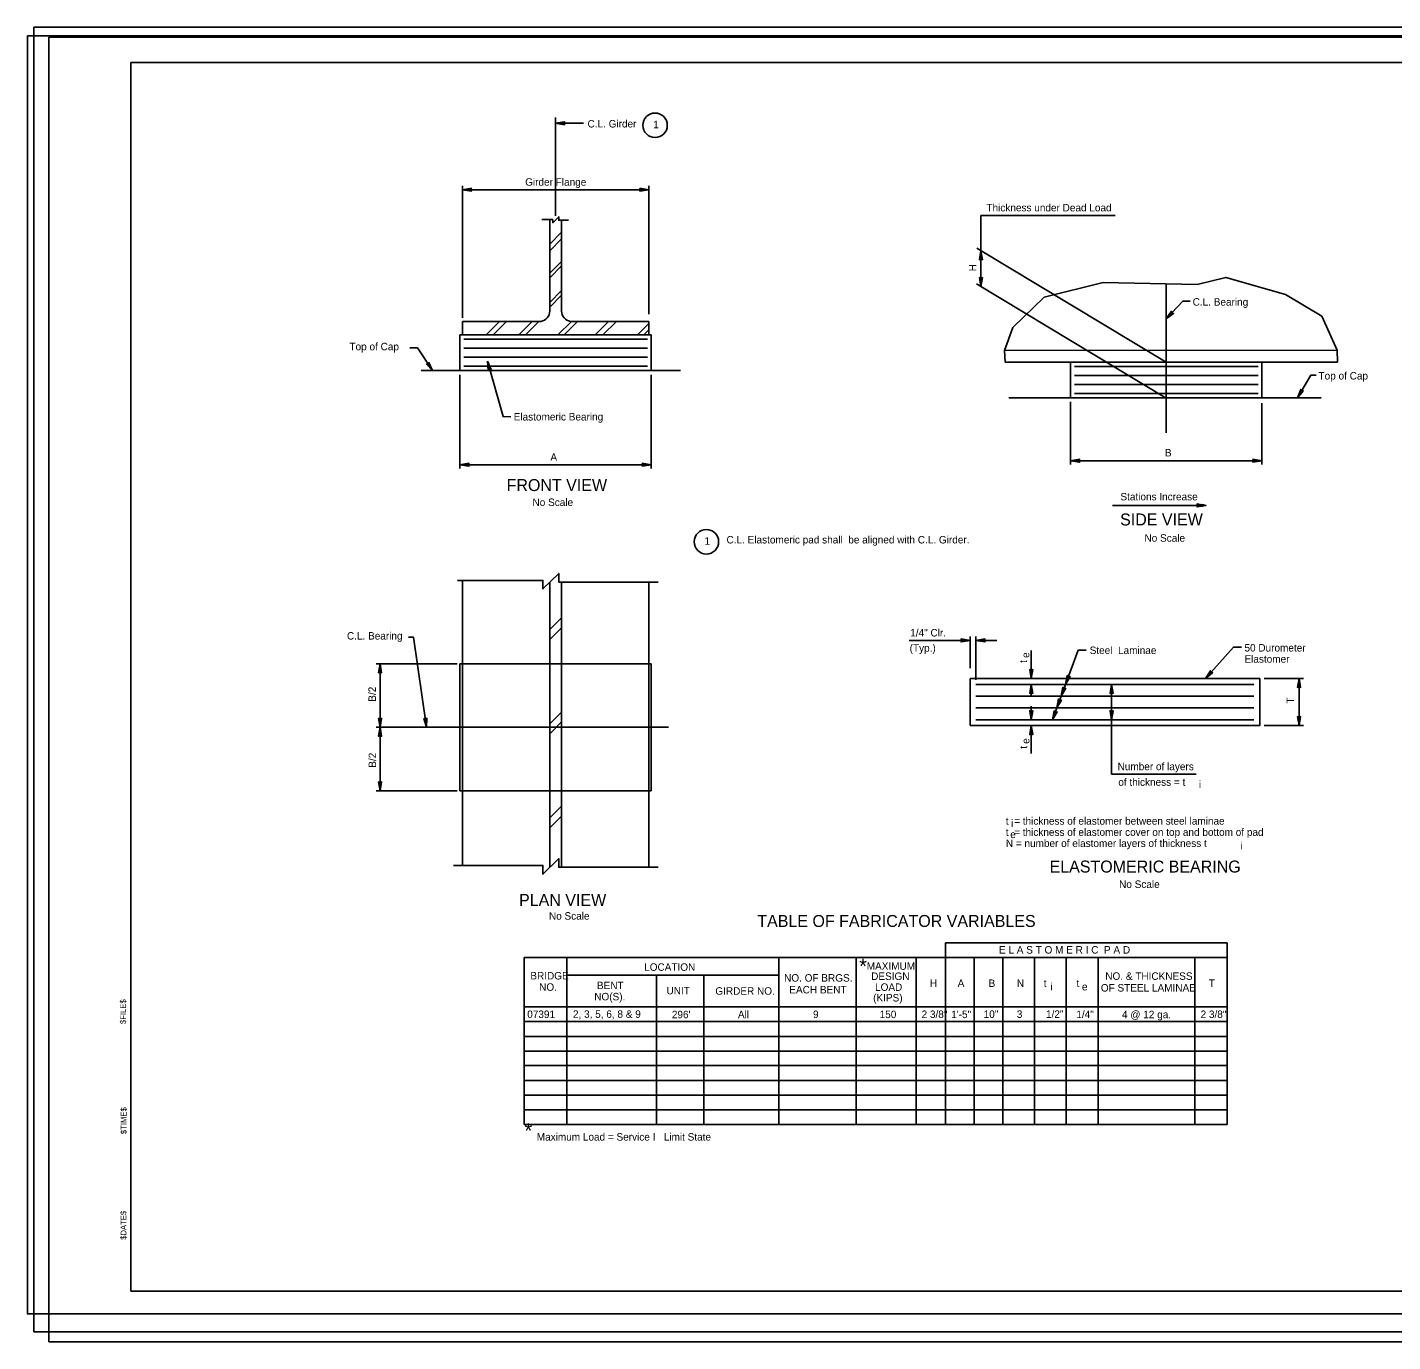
# Model space of a CAD drawing. Extents: x -194 to 226, y 505 to 725.
# Drawn here: x -193.6 to 34.6, y 505.4 to 725.2 of the extents above; entities that cross this region are included whole.
import ezdxf

# ---------------------------------------------------------------- set-up
doc = ezdxf.new("R2010")
doc.units = 0
for name, color, linetype in [('border', 7, 'Continuous'), ('Border 2660-Hwy18 - Level 62', 7, 'Continuous'), ('Border 2660-Hwy18 - Level 63', 7, 'Continuous'), ('Dimensions', 7, 'Continuous'), ('Level 20', 7, 'Continuous'), ('Level 21', 7, 'Continuous'), ('Level 31', 7, 'Continuous'), ('Level 40', 7, 'Continuous'), ('Level 41', 7, 'Continuous'), ('Level 42', 7, 'Continuous'), ('Level 43', 7, 'Continuous'), ('Level 58', 7, 'Continuous'), ('Level 62 PDF', 7, 'Continuous')]:
    doc.layers.add(name, color=color, linetype=linetype)

# ---------------------------------------------------------------- blocks, each defined once
blk = doc.blocks.new('ARROW')
at = {"layer": 'Level 58'}
blk.add_lwpolyline([(-1.2, 0.251), (0, 0), (-1.2, -0.251), (-1.004, 0)], close=True, dxfattribs=at)

msp = doc.modelspace()

# ---------------------------------------------------------------- linework, layer by layer
at = {"layer": 'border'}
for p, q in [((-176.33, 719.31), (143.78, 719.31)), ((-176.33, 513.86), (-176.33, 719.31)), ((143.78, 513.86), (-176.33, 513.86))]:
    msp.add_line(p, q, dxfattribs=at)
at = {"layer": 'Border 2660-Hwy18 - Level 62'}
msp.add_lwpolyline([(-192.53, 725.17), (148.65, 725.17), (148.65, 507.07), (-192.53, 507.07)], close=True, dxfattribs=at)
at = {"layer": 'Border 2660-Hwy18 - Level 63'}
msp.add_lwpolyline([(-193.64, 723.74), (146.35, 723.74), (146.35, 510.04), (-193.64, 510.04)], close=True, dxfattribs=at)
at = {"layer": 'Dimensions'}
for p, q in [((-129.69, 671.58), (-128.41, 671.58)), ((-128.41, 671.58), (-125.92, 667.79))]:
    msp.add_line(p, q, dxfattribs=at)
msp.add_lwpolyline([(-125.92, 667.79), (-126.51, 669.12), (-126.64, 668.89), (-126.91, 668.86)], close=True, dxfattribs=at)
at = {"layer": 'Level 20'}
for p, q in [((-105.35, 693.67), (-105.35, 710.08)), ((-3.29, 657.38), (-3.29, 682.35)), ((-135.32, 608.13), (-86.47, 608.13))]:
    msp.add_line(p, q, dxfattribs=at)
at = {"layer": 'Level 21'}
for p, q in [((-84.47, 667.79), (-127.81, 667.79)), ((22.62, 663.21), (-29.62, 663.21))]:
    msp.add_line(p, q, dxfattribs=at)
at = {"layer": 'Level 31'}
for p, q in [((-106.33, 693.03), (-106.33, 677.74)), ((-104.36, 692.92), (-104.36, 677.74)), ((-107.8, 675.98), (-120.93, 675.98)), ((-120.93, 673.75), (-120.93, 675.98)), ((-102.89, 675.98), (-89.76, 675.98)), ((-89.76, 673.75), (-89.76, 675.98)), ((-121.33, 673.75), (-104.36, 673.75)), ((-121.33, 667.79), (-121.33, 673.75)), ((-89.37, 673.75), (-106.33, 673.75)), ((-89.37, 667.79), (-89.37, 673.75)), ((-120.68, 673.01), (-90.01, 673.01)), ((-120.68, 671.52), (-90.01, 671.52)), ((-30.3, 671.15), (25.29, 671.16)), ((-120.68, 670.02), (-90.01, 670.02)), ((-30.24, 669.17), (25.35, 669.19)), ((-19.27, 663.21), (-19.27, 669.17)), ((12.69, 663.21), (12.69, 669.17)), ((-120.68, 668.53), (-90.01, 668.53)), ((-18.62, 668.43), (12.05, 668.43)), ((-18.62, 666.94), (12.05, 666.94)), ((-18.62, 665.45), (12.05, 665.45)), ((-18.62, 663.95), (12.05, 663.95)), ((-120.93, 585.03), (-120.93, 632.7)), ((-106.33, 632.38), (-106.33, 584.69)), ((-104.36, 632.42), (-104.36, 584.74)), ((-89.76, 584.74), (-89.76, 632.42)), ((-121.33, 618.76), (-121.33, 597.5)), ((-120.93, 618.76), (-121.33, 618.76)), ((-120.93, 618.76), (-89.76, 618.76)), ((-89.76, 618.76), (-89.37, 618.76)), ((-89.37, 618.76), (-89.37, 597.5)), ((-36.07, 616.29), (12.33, 616.29)), ((-36.07, 616.29), (-36.07, 608.42)), ((12.33, 616.29), (12.33, 608.42)), ((-35.09, 615.31), (11.33, 615.31)), ((-35.09, 613.34), (-20.87, 613.34)), ((-20.87, 613.34), (11.33, 613.34)), ((-35.09, 611.37), (11.33, 611.37)), ((-35.09, 609.4), (-22.31, 609.4)), ((-22.31, 609.4), (11.33, 609.4)), ((-36.07, 608.42), (12.33, 608.42)), ((-120.93, 597.5), (-121.33, 597.5)), ((-120.93, 597.5), (-89.76, 597.5)), ((-89.76, 597.5), (-89.37, 597.5))]:
    msp.add_line(p, q, dxfattribs=at)
for centre, start, end in [((-108.1, 677.73), 279.5, 0), ((-102.59, 677.73), 180, 260.5)]:
    msp.add_arc(centre, 1.76, start, end, dxfattribs=at)
at = {"layer": 'Level 40'}
for p, q in [((-103.46, 569.66), (-103.46, 541.74)), ((-68.06, 569.66), (-68.06, 541.74)), ((-55.1, 569.66), (-55.1, 541.74)), ((-45.11, 569.66), (-45.11, 541.74)), ((-35.38, 569.66), (-35.38, 541.74)), ((-30.59, 569.66), (-30.59, 541.74)), ((-25.3, 569.66), (-25.3, 541.74)), ((-20.03, 569.66), (-20.03, 541.74)), ((-14.65, 569.66), (-14.65, 541.74)), ((1.49, 569.66), (1.49, 541.74)), ((-103.46, 566.68), (-68.06, 566.68)), ((-88.46, 566.68), (-88.46, 541.74)), ((-80.56, 566.68), (-80.56, 541.74)), ((-110.62, 561.37), (6.87, 561.37)), ((6.87, 561.87), (6.87, 558.38)), ((-110.62, 558.92), (6.87, 558.92)), ((-110.62, 556.46), (6.87, 556.46)), ((-110.62, 554.01), (6.87, 554.01)), ((-110.62, 551.56), (6.87, 551.56)), ((-110.62, 549.1), (6.87, 549.1)), ((-110.62, 546.65), (6.87, 546.65)), ((-110.62, 544.2), (6.87, 544.2))]:
    msp.add_line(p, q, dxfattribs=at)
for centre in [(-88.73, 708.78), (-80.15, 639.15)]:
    msp.add_circle(centre, 2.05, dxfattribs=at)
at = {"layer": 'Level 41'}
for p, q in [((-40.17, 572.11), (-40.17, 541.74)), ((-40.17, 572.11), (6.87, 572.11)), ((6.87, 572.11), (6.87, 541.74)), ((-110.62, 569.66), (6.87, 569.66)), ((-110.62, 569.66), (-110.62, 541.74)), ((-110.62, 541.74), (6.87, 541.74))]:
    msp.add_line(p, q, dxfattribs=at)
at = {"layer": 'Level 42'}
for p, q in [((-106.33, 688.92), (-104.36, 690.89)), ((-106.33, 687.82), (-104.36, 689.81)), ((-106.33, 684.07), (-104.36, 686.03)), ((-106.33, 683.3), (-104.36, 685.27)), ((-106.33, 679.18), (-104.36, 681.15)), ((-106.33, 678.37), (-104.36, 680.37)), ((-116.93, 673.75), (-114.7, 675.98)), ((-115.8, 673.75), (-113.57, 675.98)), ((-111.5, 673.75), (-109.28, 675.98)), ((-110.4, 673.75), (-108.18, 675.98)), ((-104.95, 673.75), (-102.71, 675.98)), ((-103.92, 673.75), (-101.69, 675.98)), ((-98.73, 673.75), (-96.52, 675.98)), ((-97.43, 673.75), (-95.2, 675.98)), ((-91.64, 673.75), (-89.76, 675.66)), ((-90.59, 673.75), (-89.76, 674.59)), ((-106.33, 624.46), (-104.36, 626.43)), ((-106.33, 622.79), (-104.36, 624.78)), ((-106.33, 608.72), (-104.36, 610.69)), ((-106.33, 607.04), (-104.36, 609.04)), ((-106.33, 592.98), (-104.36, 594.94)), ((-106.33, 591.3), (-104.36, 593.29))]:
    msp.add_line(p, q, dxfattribs=at)
at = {"layer": 'Level 43'}
for p, q in [((-100.7, 709.12), (-105.35, 709.12)), ((-120.93, 676.61), (-120.93, 698.64)), ((-89.76, 677.19), (-89.76, 698.64)), ((-120.93, 698), (-89.76, 698)), ((-11.84, 693.7), (-34.28, 693.7)), ((-34.28, 693.7), (-34.28, 691.97)), ((-34.28, 681.83), (-34.28, 691.97)), ((-3.29, 669.17), (-34.96, 688.23)), ((-3.29, 663.18), (-35, 682.26)), ((-121.33, 667.04), (-121.33, 651.4)), ((-89.37, 667.04), (-89.37, 651.4)), ((-19.27, 662.56), (-19.27, 652.06)), ((12.69, 662.31), (12.69, 652.06)), ((-19.27, 652.71), (12.69, 652.71)), ((-121.33, 652.04), (-89.37, 652.04)), ((-36.07, 618.02), (-36.07, 623.31)), ((-35.09, 616.05), (-35.09, 623.31)), ((-46.28, 622.67), (-36.07, 622.67)), ((-31.6, 622.67), (-35.09, 622.67)), ((-25.85, 621), (-25.85, 616.29)), ((-121.82, 618.76), (-135.32, 618.76)), ((-134.68, 608.13), (-134.68, 618.76)), ((13.06, 616.29), (19.66, 616.29)), ((18.91, 608.42), (18.91, 616.29)), ((-25.85, 615.31), (-25.85, 613.23)), ((-12.42, 607.44), (-12.42, 615.31)), ((-25.85, 609.4), (-25.85, 611.68)), ((-134.68, 597.5), (-134.68, 608.13)), ((-25.85, 603.73), (-25.85, 608.42)), ((-12.42, 607.44), (-12.42, 600.28)), ((13.06, 608.42), (19.66, 608.42)), ((-12.42, 600.28), (1.69, 600.28)), ((-121.79, 597.5), (-135.32, 597.5))]:
    msp.add_line(p, q, dxfattribs=at)
for points in [[(-105.35, 709.12), (-103.85, 708.87), (-103.98, 709.12), (-103.85, 709.37)], [(-120.93, 698), (-119.43, 697.75), (-119.56, 698), (-119.43, 698.25)], [(-89.76, 698), (-91.26, 698.25), (-91.13, 698), (-91.26, 697.75)], [(-34.28, 687.81), (-34.53, 686.31), (-34.28, 686.44), (-34.03, 686.31)], [(-34.28, 681.83), (-34.03, 683.33), (-34.28, 683.2), (-34.53, 683.33)], [(-3.29, 676.42), (-2.08, 677.34), (-2.35, 677.42), (-2.44, 677.68)], [(-116.74, 669.37), (-116.62, 667.86), (-116.41, 668.04), (-116.13, 667.98)], [(18.64, 663.21), (19.61, 664.37), (19.33, 664.39), (19.18, 664.63)], [(-19.27, 652.71), (-17.77, 652.46), (-17.9, 652.71), (-17.77, 652.96)], [(12.69, 652.71), (11.19, 652.96), (11.32, 652.71), (11.19, 652.46)], [(-121.33, 652.04), (-119.83, 651.79), (-119.96, 652.04), (-119.83, 652.29)], [(-89.37, 652.04), (-90.87, 652.29), (-90.74, 652.04), (-90.87, 651.79)], [(3.35, 645.23), (1.85, 645.48), (1.98, 645.23), (1.85, 644.98)], [(-36.07, 622.67), (-37.57, 622.92), (-37.44, 622.67), (-37.57, 622.42)], [(-35.09, 622.67), (-33.59, 622.42), (-33.72, 622.67), (-33.59, 622.92)], [(-134.68, 618.76), (-134.93, 617.26), (-134.68, 617.39), (-134.43, 617.26)], [(-25.85, 616.29), (-25.6, 617.79), (-25.85, 617.66), (-26.1, 617.79)], [(-20.12, 615.31), (-19.37, 616.63), (-19.65, 616.59), (-19.84, 616.8)], [(3.27, 616.29), (4.46, 617.25), (4.18, 617.32), (4.08, 617.58)], [(18.91, 616.29), (18.66, 614.79), (18.91, 614.92), (19.16, 614.79)], [(-25.85, 615.31), (-26.1, 613.81), (-25.85, 613.94), (-25.6, 613.81)], [(-20.84, 613.34), (-20.09, 614.66), (-20.37, 614.63), (-20.56, 614.83)], [(-12.42, 615.31), (-12.67, 613.81), (-12.42, 613.94), (-12.17, 613.81)], [(-21.56, 611.37), (-20.81, 612.69), (-21.09, 612.66), (-21.28, 612.87)], [(-134.68, 608.13), (-134.43, 609.63), (-134.68, 609.5), (-134.93, 609.63)], [(-126.9, 608.13), (-126.87, 609.65), (-127.09, 609.49), (-127.36, 609.58)], [(-25.85, 609.4), (-25.6, 610.9), (-25.85, 610.77), (-26.1, 610.9)], [(-22.28, 609.4), (-21.53, 610.73), (-21.81, 610.69), (-22, 610.9)], [(-12.42, 609.4), (-12.17, 610.9), (-12.42, 610.77), (-12.67, 610.9)], [(18.91, 608.42), (19.16, 609.92), (18.91, 609.79), (18.66, 609.92)], [(-134.68, 608.13), (-134.93, 606.63), (-134.68, 606.76), (-134.43, 606.63)], [(-25.85, 608.42), (-26.1, 606.92), (-25.85, 607.05), (-25.6, 606.92)], [(-134.68, 597.5), (-134.43, 599), (-134.68, 598.87), (-134.93, 599)]]:
    msp.add_lwpolyline(points, close=True, dxfattribs=at)
for points in [[(-107.66, 693.03), (-105.84, 693.03), (-105.84, 692.48), (-104.83, 693.49), (-104.83, 692.92), (-103.19, 692.92)], [(-30.24, 669.17), (-30.3, 671.13), (-28.92, 674.99), (-23.67, 680.04), (-13.85, 682.48), (1.87, 682.19), (6.66, 683.36), (16.66, 680.5), (22.71, 676.85), (25.29, 671.16), (25.35, 669.19)], [(0.68, 679.37), (-0.51, 679.37), (-3.29, 676.42)], [(-116.74, 669.37), (-114.12, 660.07), (-112.81, 660.06)], [(21.79, 667.02), (20.88, 667.02), (18.64, 663.21)], [(-12.3, 645.23), (3.35, 645.23)], [(-121.72, 632.7), (-107.46, 632.7), (-107.46, 631.26), (-104.83, 633.87), (-104.83, 632.42), (-88.23, 632.42)], [(-129.95, 623.21), (-129.11, 623.21), (-126.9, 608.13)], [(-20.12, 615.31), (-18.03, 621.01), (-16.69, 621.01)], [(3.27, 616.29), (7.92, 621.54), (9.26, 621.54)], [(-20.84, 613.34), (-20.12, 615.31)], [(-21.56, 611.37), (-20.84, 613.34)], [(-22.28, 609.4), (-21.56, 611.37)], [(-122.39, 585.03), (-107.46, 585.03), (-107.46, 583.57), (-104.83, 586.18), (-104.83, 584.74), (-88.23, 584.74)]]:
    msp.add_lwpolyline(points, dxfattribs=at)
at = {"layer": 'Level 62 PDF'}
msp.add_lwpolyline([(-190.03, 723.5), (151.15, 723.5), (151.15, 505.41), (-190.03, 505.41)], close=True, dxfattribs=at)

# ---------------------------------------------------------------- block references
at = {"layer": 'Level 43', "xscale": 0.5247989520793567, "yscale": 0.5247989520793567}
msp.add_blockref('ARROW', (3.35, 645.23), dxfattribs=at)

# ---------------------------------------------------------------- texts
at = {"layer": 'border'}
for s, p in [('$FILE$', (-177.16, 558.52)), ('$TIME$', (-177.06, 540.11)), ('$DATE$', (-177.1, 522.44))]:
    msp.add_text(s, height=0.96, rotation=89.9999, dxfattribs=at).set_placement(p)
at = {"layer": 'Level 40'}
for s, height, p in [('C.L. Girder', 1.25, (-100.01, 708.42)), ('1', 1.25, (-89.04, 708.3)), ('Girder Flange', 1.25, (-110.44, 698.68)), ('Thickness under Dead Load', 1.25, (-33.34, 694.39)), ('C.L. Bearing', 1.25, (1.12, 678.63)), ('Top of Cap', 1.25, (-139.8, 671.17)), ('Top of Cap', 1.25, (22.16, 666.28)), ('Elastomeric Bearing', 1.25, (-112.35, 659.43)), ('A', 1.25, (-106.22, 652.69)), ('B', 1.25, (-3.51, 653.41)), ('No Scale', 1.25, (-109.21, 645.13)), ('Stations Increase', 1.25, (-10.95, 646.07)), ('1', 1.25, (-80.46, 638.66)), ('C.L. Elastomeric pad shall  be aligned with C.L. Girder.', 1.25, (-76.78, 638.87)), ('No Scale', 1.25, (-6.93, 639.16)), ('C.L. Bearing', 1.25, (-140.22, 622.8)), ('1/4" Clr.', 1.25, (-46.08, 623.32)), ('(Typ.)', 1.25, (-46.18, 620.77)), ('Steel  Laminae', 1.25, (-16.09, 620.38)), ('50 Durometer', 1.25, (9.78, 620.8)), ('Elastomer', 1.25, (9.78, 618.93)), ('Number of layers', 1.25, (-11.42, 600.96)), ('of thickness = t', 1.25, (-11.3, 598.35)), ('i', 1.25, (2.17, 597.99)), ('t  = thickness of elastomer between steel laminae', 1.25, (-30.1, 591.85)), ('t  = thickness of elastomer cover on top and bottom of pad', 1.25, (-30.1, 589.98)), ('i', 1.25, (-29.24, 591.47)), ('N = number of elastomer layers of thickness t', 1.25, (-30.1, 588.12)), ('e', 1.25, (-29.36, 589.6)), ('i', 1.25, (9.07, 587.72)), ('No Scale', 1.25, (-11.17, 581.27)), ('No Scale', 1.25, (-106.46, 575.97)), ('E L A S T O M E R I C  P A D', 1.25, (-31.25, 570.3)), ('LOCATION', 1.25, (-90.55, 567.42)), ('*', 2.5, (-54.62, 566.95)), ('MAXIMUM', 1.25, (-53.35, 567.59)), ('BRIDGE', 1.25, (-109.57, 565.97)), ('NO. OF BRGS.', 1.25, (-67.16, 565.61)), ('DESIGN', 1.25, (-52.61, 565.89)), ('H', 1.25, (-42.79, 564.72)), ('A', 1.25, (-38.15, 564.72)), ('B', 1.25, (-32.99, 564.72)), ('N', 1.25, (-28.26, 564.72)), ('NO. & THICKNESS', 1.25, (-13.48, 565.91)), ('T', 1.25, (3.83, 564.72)), ('NO.', 1.25, (-108.1, 564.08)), ('NO(S).', 1.25, (-98.89, 562.48)), ('BENT', 1.25, (-98.43, 564.35)), ('UNIT', 1.25, (-86.82, 563.48)), ('GIRDER NO.', 1.25, (-78.65, 563.42)), ('EACH BENT', 1.25, (-66.29, 563.64)), ('LOAD', 1.25, (-51.96, 564.07)), ('t ', 1.25, (-23.76, 564.72)), ('i', 1.25, (-22.65, 564.14)), ('t ', 1.25, (-18.29, 564.72)), ('e', 1.25, (-17.38, 564.14)), ('OF STEEL LAMINAE', 1.25, (-14.22, 563.95)), ('(KIPS)', 1.25, (-52.28, 562.29)), ('07391', 1.25, (-110.09, 559.53)), ('2, 3, 5, 6, 8 & 9', 1.25, (-102.45, 559.56)), ("296'", 1.25, (-85.92, 559.49)), ('All', 1.25, (-74.88, 559.49)), ('9', 1.25, (-62.33, 559.53)), ('150', 1.25, (-51.19, 559.51)), ('2 3/8"', 1.25, (-44.18, 559.53)), ('1\'-5"', 1.25, (-39.23, 559.51)), ('10"', 1.25, (-33.81, 559.55)), ('3', 1.25, (-28.27, 559.55)), ('1/2"', 1.25, (-23.39, 559.55)), ('1/4"', 1.25, (-18.32, 559.52)), ('4 @ 12 ga.', 1.25, (-10.69, 559.49)), ('2 3/8"', 1.25, (2.45, 559.53)), ('*', 2.5, (-110.55, 539.44)), ('Maximum Load = Service I   Limit State', 1.25, (-108.5, 539.03))]:
    msp.add_text(s, height=height, dxfattribs=at).set_placement(p)
for s, p in [('H', (-35.02, 684.37)), ('t', (-26.55, 618.9)), ('e', (-26.18, 619.73)), ('B/2', (-135.38, 612.41)), ('T', (18.06, 612.09)), ('t', (-26.53, 604.55)), ('e', (-26.16, 605.37)), ('B/2', (-135.35, 601.37))]:
    msp.add_text(s, height=1.25, rotation=90, dxfattribs=at).set_placement(p)
at = {"layer": 'Level 41'}
for s, p in [(' FRONT VIEW ', (-114.28, 647.63)), (' SIDE VIEW ', (-11.75, 641.88)), (' ELASTOMERIC BEARING ', (-23.54, 583.85)), (' PLAN VIEW ', (-112.2, 578.26)), (' TABLE OF FABRICATOR VARIABLES ', (-72.38, 574.75))]:
    msp.add_text(s, height=2, dxfattribs=at).set_placement(p)

doc.saveas('drawing.dxf')
